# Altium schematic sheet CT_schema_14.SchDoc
size 390 x 278 mm
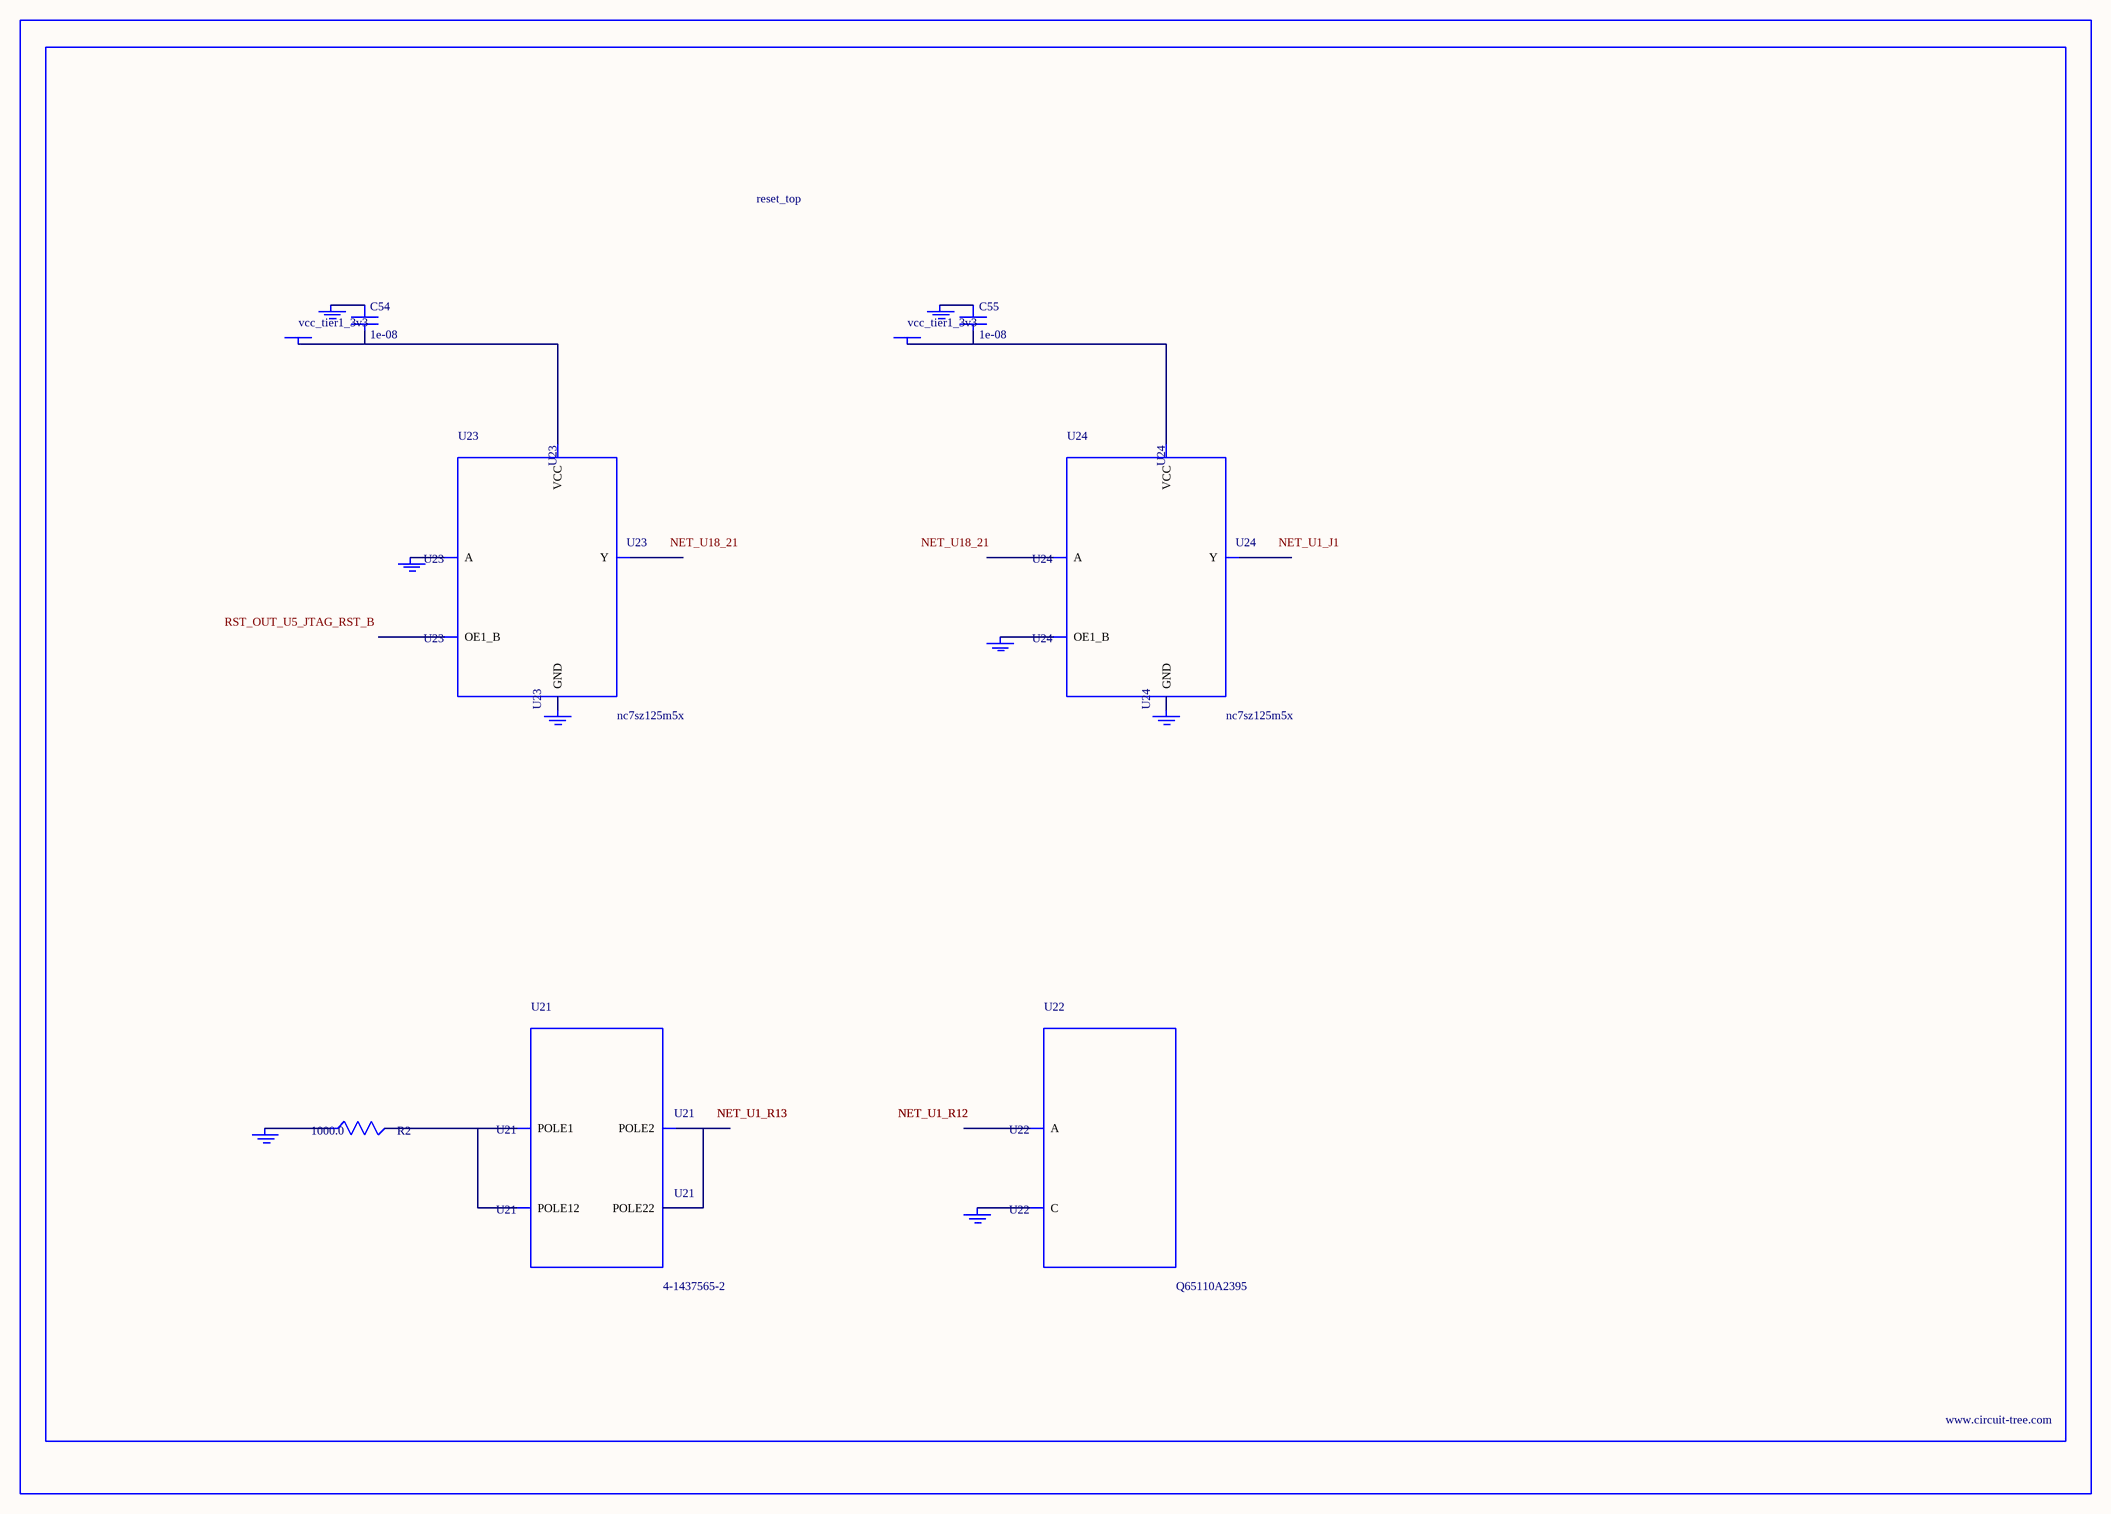
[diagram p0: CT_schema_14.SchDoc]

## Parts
BORDER13  (no value)
C54  1e-08  [C0402]
C55  1e-08  [C0402]
GND_INSTANCE_13_0  (no value)
GND_INSTANCE_13_1  (no value)
GND_INSTANCE_13_2  (no value)
GND_INSTANCE_13_3  (no value)
GND_INSTANCE_13_4  (no value)
GND_INSTANCE_13_5  (no value)
GND_INSTANCE_13_6  (no value)
GND_INSTANCE_13_7  (no value)
POWER_INSTANCE_13_0  vcc_tier1_3v3
POWER_INSTANCE_13_1  vcc_tier1_3v3
R2  1000.0  [R0603]
U21  4-1437565-2  [SW_4-1437565-2]
U22  Q65110A2395  [LGM67K-G1J2-24-Z]
U23  nc7sz125m5x  [NC7SZ125M5X]
U24  nc7sz125m5x  [NC7SZ125M5X]

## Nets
NetC54_1: C54.1 GND_INSTANCE_13_2.0(GND)
NetC54_2: C54.2 POWER_INSTANCE_13_0.0(PWR) U23.5(VCC)
NetC55_1: C55.1 GND_INSTANCE_13_5.0(GND)
NetC55_2: C55.2 POWER_INSTANCE_13_1.0(PWR) U24.5(VCC)
NetGND_INSTANCE_13_0_0: GND_INSTANCE_13_0.0(GND) R2.1
NetGND_INSTANCE_13_1_0: GND_INSTANCE_13_1.0(GND) U22.C
NetGND_INSTANCE_13_3_0: GND_INSTANCE_13_3.0(GND) U23.2(A)
NetGND_INSTANCE_13_4_0: GND_INSTANCE_13_4.0(GND) U23.3(GND)
NetGND_INSTANCE_13_6_0: GND_INSTANCE_13_6.0(GND) U24.1(OE1_B)
NetGND_INSTANCE_13_7_0: GND_INSTANCE_13_7.0(GND) U24.3(GND)
NetR2_2: R2.2 U21.1(POLE1) U21.2(POLE12)
NetU21_3: U21.3(POLE2) U21.4(POLE22)

Not connected (* = marked no-connect by the designer): U22 A; U23 1(OE1_B) 4(Y); U24 2(A) 4(Y)

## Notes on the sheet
- Labels drawn without touching a wire or pin: NET_U1_J1, NET_U18_21, RST_OUT_U5_JTAG_RST_B

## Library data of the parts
BORDER13 = BORDER_PAGE13
C54 C55 = C0402C103K3RAC
GND_INSTANCE_13_0-GND_INSTANCE_13_7 = GND
POWER_INSTANCE_13_0 POWER_INSTANCE_13_1 = PWR
R2 = RC0603JR-071KL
